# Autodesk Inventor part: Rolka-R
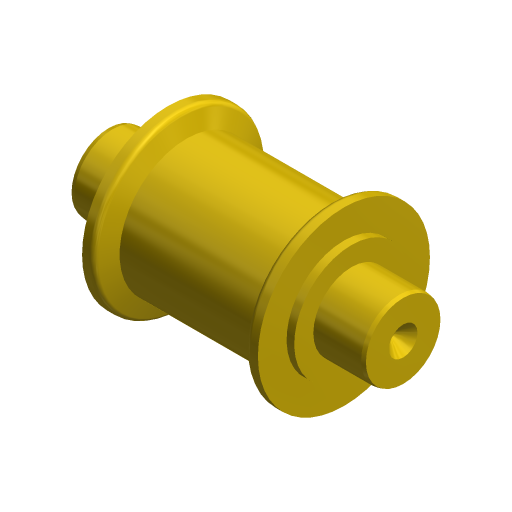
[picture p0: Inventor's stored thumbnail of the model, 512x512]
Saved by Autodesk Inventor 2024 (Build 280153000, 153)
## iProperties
Company: ATC
Shininess: 20.0
Length Units: 11269
Angle Units: 11279
Time Units: 11290
Mass Units: 11283
Length Display Precision: 3
Angle Display Precision: 2
Compacted: True
Created: 2023-03
Part Number: Rolka-R
Document SubType Name: Modeling
Designer: Andrzej Jaskulski
Material: ZŁOTO-POLER
Density: 19.3 g/cm^3
Appearance: Lśniąca - złota
Checked By: A.J.
Engr Approved By: Andrzej Jaskulski
Mfg Approved By: Andrzej Jaskulski
Authority: A.J.
Density: 0.0
Volumn: 0.0
Area: 0.0
PropertySet Name: Model Information
Control State: 0
Master: False
Checked Out: False
Title: A.J.: Kurs R2024-MEP
Author: Andrzej Jaskulski
Revision Number: 1/24
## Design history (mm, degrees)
node "Revolution1" dims "d7" = 90 deg
  sketch "Sketch1"
    geometry: L1 (134.146, 50)-(122.146, 50); L2 (122.146, 50)-(114.866, 30); L3 (114.866, 30)-(-30.575, 30); L4 (-30.575, 30)-(-37.854, 50); L5 (-37.854, 50)-(-49.854, 50); L6 (134.146, 50)-(134.146, 20); L7 (134.146, 20)-(142.146, 20); L8 (142.146, 20)-(142.146, -40); L9 (-49.854, 50)-(-49.854, 20); L10 (-49.854, 20)-(-57.854, 20); L11 (-57.854, 20)-(-57.854, -40); L12 (-57.854, -40)-(142.146, -40) reference
    constraints: 24 end point, 4 equal length, 4 parallel, 3 perpendicular, 1 horizontal
    dimensions: "d2" = 12 distance of L1.start L1.end; "d4" = 110 deg angle of L3 L2; "d5" = 184 distance of L1.start L5.end (derived); "d12" = 70 distance between parallel lines of L3 L12; "d13" = 90 distance between parallel lines of L12 L1; "d14" = 60 distance of L7.end L8.end; "d15" = 8 distance of L6.end L7.end; "d39" = 110 deg angle of L4 L3 (= d4)
node "Fillet1" dims "d8" = 6
node "Extrusion1" dims "d16" = 0, "d17" = 54
node "Hole1" dims "d19" = 120 deg, "d20" = 90 deg, "d21" = 2, "d22" = 30, "d23" = 26, "d24" = 6
node "Chamfer2" dims "d25" = 1, "d26" = 4, "d41" = 45 deg
node "Extrusion2" dims "d27" = 0, "d28" = 54
node "Hole2" dims "d30" = 120 deg, "d31" = 90 deg, "d32" = 2, "d33" = 30, "d34" = 26, "d35" = 12
node "Chamfer3" dims "d36" = 1, "d37" = 4, "d42" = 45 deg
node "Bryła1"
node "Korpusy bryłowe"
node "Korpusy powierzchniowe"
sketch "Sketch2"
  geometry: C1 r 12.5 at (0, 0); C2 r 40 at (0, 0)
  constraints: 2 centre point, 1 coincident
  dimensions: "d18" = 80 diameter of C2
sketch "Sketch3"
  geometry: C1 r 40 at (0, 0) reference; 1 further point
  constraints: 1 coincident
sketch "Sketch4"
  geometry: C1 r 12.5 at (0, 0); C2 r 40 at (0, 0)
  constraints: 2 centre point, 1 coincident
  dimensions: "d29" = 80 diameter of C2
sketch "Sketch5"
  geometry: C1 r 40 at (0, 0) reference; 1 further point
  constraints: 1 coincident
